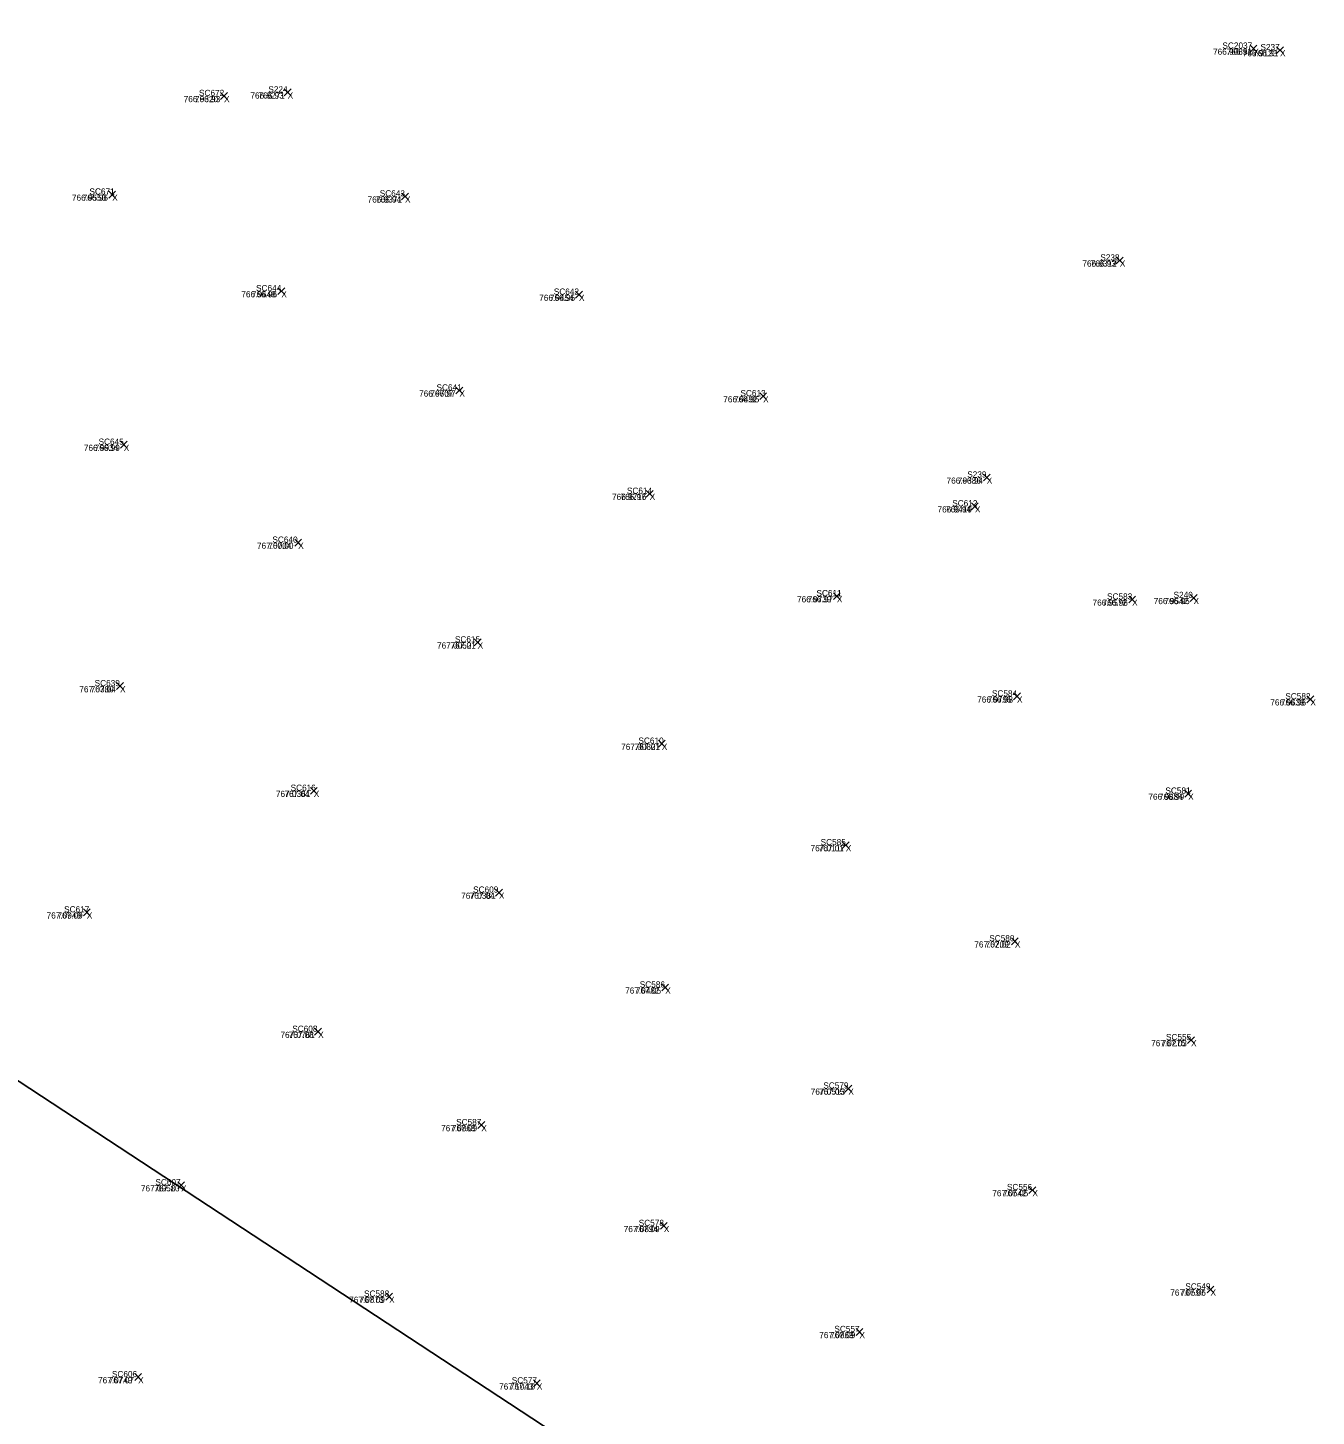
# Model space of a CAD drawing. Extents: x 1845019 to 1877956, y 680444 to 701081.
# Drawn here: x 1857624.26 to 1857636.8, y 694302.54 to 694316.04 of the extents above; entities that cross this region are included whole.
import ezdxf

# ---------------------------------------------------------------- set-up
doc = ezdxf.new("R2010")
doc.units = 0
for name, color, linetype in [('SV_X_CL_Survey_20', 7, 'Continuous'), ('SV_X_Random_Point', 7, 'Continuous'), ('SV_X_Text_Comment', 7, 'Continuous'), ('SV_X_Text_Elevation', 7, 'Continuous'), ('SV_X_Text_Name', 7, 'Continuous')]:
    doc.layers.add(name, color=color, linetype=linetype)

msp = doc.modelspace()

# ---------------------------------------------------------------- linework, layer by layer
at = {"layer": 'SV_X_CL_Survey_20'}
msp.add_line((1856038.267, 695346.314), (1858797.327, 693536.085), dxfattribs=at)
at = {"layer": 'SV_X_Random_Point'}
for p, q in [((1857636.153, 694315.809), (1857636.219, 694315.876)), ((1857636.153, 694315.876), (1857636.219, 694315.809)), ((1857636.153, 694315.809), (1857636.219, 694315.876)), ((1857636.153, 694315.876), (1857636.219, 694315.809)), ((1857636.411, 694315.794), (1857636.477, 694315.86)), ((1857636.411, 694315.86), (1857636.477, 694315.794)), ((1857636.411, 694315.794), (1857636.477, 694315.86)), ((1857636.411, 694315.86), (1857636.477, 694315.794)), ((1857626.14, 694315.347), (1857626.207, 694315.414)), ((1857626.14, 694315.414), (1857626.207, 694315.347)), ((1857626.14, 694315.347), (1857626.207, 694315.414)), ((1857626.14, 694315.414), (1857626.207, 694315.347)), ((1857626.758, 694315.383), (1857626.825, 694315.45)), ((1857626.758, 694315.45), (1857626.825, 694315.383)), ((1857626.758, 694315.383), (1857626.825, 694315.45)), ((1857626.758, 694315.45), (1857626.825, 694315.383)), ((1857625.053, 694314.388), (1857625.119, 694314.455)), ((1857625.053, 694314.455), (1857625.119, 694314.388)), ((1857625.053, 694314.388), (1857625.119, 694314.455)), ((1857625.053, 694314.455), (1857625.119, 694314.388)), ((1857627.9, 694314.371), (1857627.967, 694314.437)), ((1857627.9, 694314.437), (1857627.967, 694314.371)), ((1857627.9, 694314.371), (1857627.967, 694314.437)), ((1857627.9, 694314.437), (1857627.967, 694314.371)), ((1857634.852, 694313.747), (1857634.919, 694313.814)), ((1857634.852, 694313.814), (1857634.919, 694313.747)), ((1857634.852, 694313.747), (1857634.919, 694313.814)), ((1857634.852, 694313.814), (1857634.919, 694313.747)), ((1857626.697, 694313.449), (1857626.764, 694313.516)), ((1857626.697, 694313.516), (1857626.764, 694313.449)), ((1857626.697, 694313.449), (1857626.764, 694313.516)), ((1857626.697, 694313.516), (1857626.764, 694313.449)), ((1857629.593, 694313.414), (1857629.659, 694313.481)), ((1857629.593, 694313.481), (1857629.659, 694313.414)), ((1857629.593, 694313.414), (1857629.659, 694313.481)), ((1857629.593, 694313.481), (1857629.659, 694313.414)), ((1857628.429, 694312.482), (1857628.496, 694312.549)), ((1857628.429, 694312.549), (1857628.496, 694312.482)), ((1857628.429, 694312.482), (1857628.496, 694312.549)), ((1857628.429, 694312.549), (1857628.496, 694312.482)), ((1857631.384, 694312.427), (1857631.451, 694312.494)), ((1857631.384, 694312.494), (1857631.451, 694312.427)), ((1857631.384, 694312.427), (1857631.451, 694312.494)), ((1857631.384, 694312.494), (1857631.451, 694312.427)), ((1857625.165, 694311.955), (1857625.232, 694312.022)), ((1857625.165, 694312.022), (1857625.232, 694311.955)), ((1857625.165, 694311.955), (1857625.232, 694312.022)), ((1857625.165, 694312.022), (1857625.232, 694311.955)), ((1857633.559, 694311.636), (1857633.626, 694311.702)), ((1857633.559, 694311.702), (1857633.626, 694311.636)), ((1857633.559, 694311.636), (1857633.626, 694311.702)), ((1857633.559, 694311.702), (1857633.626, 694311.636)), ((1857630.28, 694311.477), (1857630.347, 694311.544)), ((1857630.28, 694311.544), (1857630.347, 694311.477)), ((1857630.28, 694311.477), (1857630.347, 694311.544)), ((1857630.28, 694311.544), (1857630.347, 694311.477)), ((1857633.444, 694311.356), (1857633.51, 694311.422)), ((1857633.444, 694311.422), (1857633.51, 694311.356)), ((1857633.444, 694311.356), (1857633.51, 694311.422)), ((1857633.444, 694311.422), (1857633.51, 694311.356)), ((1857626.861, 694311.002), (1857626.928, 694311.068)), ((1857626.861, 694311.068), (1857626.928, 694311.002)), ((1857626.861, 694311.002), (1857626.928, 694311.068)), ((1857626.861, 694311.068), (1857626.928, 694311.002)), ((1857632.101, 694310.481), (1857632.167, 694310.547)), ((1857632.101, 694310.547), (1857632.167, 694310.481)), ((1857632.101, 694310.481), (1857632.167, 694310.547)), ((1857632.101, 694310.547), (1857632.167, 694310.481)), ((1857634.973, 694310.449), (1857635.04, 694310.515)), ((1857634.973, 694310.515), (1857635.04, 694310.449)), ((1857634.973, 694310.449), (1857635.04, 694310.515)), ((1857634.973, 694310.515), (1857635.04, 694310.449)), ((1857635.57, 694310.464), (1857635.637, 694310.531)), ((1857635.57, 694310.531), (1857635.637, 694310.464)), ((1857635.57, 694310.464), (1857635.637, 694310.531)), ((1857635.57, 694310.531), (1857635.637, 694310.464)), ((1857628.607, 694310.031), (1857628.674, 694310.098)), ((1857628.607, 694310.098), (1857628.674, 694310.031)), ((1857628.607, 694310.031), (1857628.674, 694310.098)), ((1857628.607, 694310.098), (1857628.674, 694310.031)), ((1857625.128, 694309.606), (1857625.195, 694309.673)), ((1857625.128, 694309.673), (1857625.195, 694309.606)), ((1857625.128, 694309.606), (1857625.195, 694309.673)), ((1857625.128, 694309.673), (1857625.195, 694309.606)), ((1857633.852, 694309.506), (1857633.919, 694309.573)), ((1857633.852, 694309.573), (1857633.919, 694309.506)), ((1857633.852, 694309.506), (1857633.919, 694309.573)), ((1857633.852, 694309.573), (1857633.919, 694309.506)), ((1857636.706, 694309.478), (1857636.773, 694309.545)), ((1857636.706, 694309.545), (1857636.773, 694309.478)), ((1857636.706, 694309.478), (1857636.773, 694309.545)), ((1857636.706, 694309.545), (1857636.773, 694309.478)), ((1857630.398, 694309.045), (1857630.464, 694309.112)), ((1857630.398, 694309.112), (1857630.464, 694309.045)), ((1857630.398, 694309.045), (1857630.464, 694309.112)), ((1857630.398, 694309.112), (1857630.464, 694309.045)), ((1857627.013, 694308.587), (1857627.08, 694308.654)), ((1857627.013, 694308.654), (1857627.08, 694308.587)), ((1857627.013, 694308.587), (1857627.08, 694308.654)), ((1857627.013, 694308.654), (1857627.08, 694308.587)), ((1857635.517, 694308.559), (1857635.584, 694308.626)), ((1857635.517, 694308.626), (1857635.584, 694308.559)), ((1857635.517, 694308.559), (1857635.584, 694308.626)), ((1857635.517, 694308.626), (1857635.584, 694308.559)), ((1857632.187, 694308.059), (1857632.254, 694308.125)), ((1857632.187, 694308.125), (1857632.254, 694308.059)), ((1857632.187, 694308.059), (1857632.254, 694308.125)), ((1857632.187, 694308.125), (1857632.254, 694308.059)), ((1857628.814, 694307.597), (1857628.881, 694307.664)), ((1857628.814, 694307.664), (1857628.881, 694307.597)), ((1857628.814, 694307.597), (1857628.881, 694307.664)), ((1857628.814, 694307.664), (1857628.881, 694307.597)), ((1857624.806, 694307.404), (1857624.873, 694307.471)), ((1857624.806, 694307.471), (1857624.873, 694307.404)), ((1857624.806, 694307.404), (1857624.873, 694307.471)), ((1857624.806, 694307.471), (1857624.873, 694307.404)), ((1857633.832, 694307.122), (1857633.899, 694307.189)), ((1857633.832, 694307.189), (1857633.899, 694307.122)), ((1857633.832, 694307.122), (1857633.899, 694307.189)), ((1857633.832, 694307.189), (1857633.899, 694307.122)), ((1857630.432, 694306.674), (1857630.498, 694306.741)), ((1857630.432, 694306.741), (1857630.498, 694306.674)), ((1857630.432, 694306.674), (1857630.498, 694306.741)), ((1857630.432, 694306.741), (1857630.498, 694306.674)), ((1857627.055, 694306.243), (1857627.122, 694306.31)), ((1857627.055, 694306.31), (1857627.122, 694306.243)), ((1857627.055, 694306.243), (1857627.122, 694306.31)), ((1857627.055, 694306.31), (1857627.122, 694306.243)), ((1857635.546, 694306.162), (1857635.612, 694306.228)), ((1857635.546, 694306.228), (1857635.612, 694306.162)), ((1857635.546, 694306.162), (1857635.612, 694306.228)), ((1857635.546, 694306.228), (1857635.612, 694306.162)), ((1857632.212, 694305.69), (1857632.279, 694305.757)), ((1857632.212, 694305.757), (1857632.279, 694305.69)), ((1857632.212, 694305.69), (1857632.279, 694305.757)), ((1857632.212, 694305.757), (1857632.279, 694305.69)), ((1857628.642, 694305.335), (1857628.709, 694305.402)), ((1857628.642, 694305.402), (1857628.709, 694305.335)), ((1857628.642, 694305.335), (1857628.709, 694305.402)), ((1857628.642, 694305.402), (1857628.709, 694305.335)), ((1857625.723, 694304.75), (1857625.79, 694304.817)), ((1857625.723, 694304.817), (1857625.79, 694304.75)), ((1857625.723, 694304.75), (1857625.79, 694304.817)), ((1857625.723, 694304.817), (1857625.79, 694304.75)), ((1857634.002, 694304.703), (1857634.069, 694304.769)), ((1857634.002, 694304.769), (1857634.069, 694304.703)), ((1857634.002, 694304.703), (1857634.069, 694304.769)), ((1857634.002, 694304.769), (1857634.069, 694304.703)), ((1857630.418, 694304.354), (1857630.484, 694304.42)), ((1857630.418, 694304.42), (1857630.484, 694304.354)), ((1857630.418, 694304.354), (1857630.484, 694304.42)), ((1857630.418, 694304.42), (1857630.484, 694304.354)), ((1857627.746, 694303.666), (1857627.813, 694303.733)), ((1857627.746, 694303.733), (1857627.813, 694303.666)), ((1857627.746, 694303.666), (1857627.813, 694303.733)), ((1857627.746, 694303.733), (1857627.813, 694303.666)), ((1857635.735, 694303.736), (1857635.801, 694303.802)), ((1857635.735, 694303.802), (1857635.801, 694303.736)), ((1857635.735, 694303.736), (1857635.801, 694303.802)), ((1857635.735, 694303.802), (1857635.801, 694303.736)), ((1857632.321, 694303.321), (1857632.387, 694303.388)), ((1857632.321, 694303.388), (1857632.387, 694303.321)), ((1857632.321, 694303.321), (1857632.387, 694303.388)), ((1857632.321, 694303.388), (1857632.387, 694303.321)), ((1857625.305, 694302.883), (1857625.371, 694302.95)), ((1857625.305, 694302.95), (1857625.371, 694302.883)), ((1857625.305, 694302.883), (1857625.371, 694302.95)), ((1857625.305, 694302.95), (1857625.371, 694302.883)), ((1857629.182, 694302.822), (1857629.249, 694302.889)), ((1857629.182, 694302.889), (1857629.249, 694302.822)), ((1857629.182, 694302.822), (1857629.249, 694302.889)), ((1857629.182, 694302.889), (1857629.249, 694302.822))]:
    msp.add_line(p, q, dxfattribs=at)

# ---------------------------------------------------------------- texts
at = {"layer": 'SV_X_Text_Comment'}
for p in [(1857636.186, 694315.782), (1857636.444, 694315.767), (1857626.174, 694315.321), (1857626.792, 694315.356), (1857625.086, 694314.362), (1857627.934, 694314.344), (1857634.886, 694313.721), (1857626.731, 694313.422), (1857629.626, 694313.388), (1857628.463, 694312.456), (1857631.417, 694312.4), (1857625.198, 694311.928), (1857633.592, 694311.609), (1857630.313, 694311.451), (1857633.477, 694311.329), (1857626.895, 694310.975), (1857632.134, 694310.454), (1857635.006, 694310.422), (1857635.603, 694310.437), (1857628.64, 694310.005), (1857625.162, 694309.579), (1857633.886, 694309.479), (1857636.74, 694309.451), (1857630.431, 694309.019), (1857627.046, 694308.561), (1857635.551, 694308.533), (1857632.221, 694308.032), (1857628.847, 694307.57), (1857624.839, 694307.378), (1857633.866, 694307.096), (1857630.465, 694306.647), (1857627.089, 694306.216), (1857635.579, 694306.135), (1857632.246, 694305.664), (1857628.676, 694305.308), (1857625.756, 694304.723), (1857634.036, 694304.676), (1857630.451, 694304.327), (1857635.768, 694303.709), (1857627.779, 694303.639), (1857632.354, 694303.295), (1857625.338, 694302.856), (1857629.216, 694302.795)]:
    msp.add_text('X', height=0.06, dxfattribs=at).set_placement(p)
at = {"layer": 'SV_X_Text_Elevation'}
for s, p in [('766.9085', (1857635.793, 694315.782)), ('766.91', (1857635.926, 694315.782)), ('766.9123', (1857636.082, 694315.767)), ('766.91', (1857636.183, 694315.767)), ('766.9320', (1857625.781, 694315.321)), ('766.93', (1857625.891, 694315.321)), ('766.9271', (1857626.43, 694315.356)), ('766.93', (1857626.509, 694315.356)), ('766.9550', (1857624.694, 694314.362)), ('766.96', (1857624.799, 694314.362)), ('766.9371', (1857627.57, 694314.344)), ('766.94', (1857627.651, 694314.344)), ('766.9312', (1857634.522, 694313.721)), ('766.93', (1857634.603, 694313.721)), ('766.9648', (1857626.342, 694313.422)), ('766.96', (1857626.444, 694313.422)), ('766.9454', (1857629.239, 694313.388)), ('766.95', (1857629.343, 694313.388)), ('766.9707', (1857628.071, 694312.456)), ('766.97', (1857628.18, 694312.456)), ('766.9492', (1857631.029, 694312.4)), ('766.95', (1857631.134, 694312.4)), ('766.9934', (1857624.81, 694311.928)), ('766.99', (1857624.915, 694311.928)), ('766.9386', (1857633.201, 694311.609)), ('766.94', (1857633.31, 694311.609)), ('766.9716', (1857629.947, 694311.451)), ('766.97', (1857630.03, 694311.451)), ('766.9419', (1857633.113, 694311.329)), ('766.94', (1857633.195, 694311.329)), ('767.0004', (1857626.494, 694310.975)), ('767.00', (1857626.604, 694310.975)), ('766.9739', (1857631.747, 694310.454)), ('766.97', (1857631.851, 694310.454)), ('766.9572', (1857634.621, 694310.422)), ('766.96', (1857634.719, 694310.422)), ('766.9542', (1857635.216, 694310.437)), ('766.95', (1857635.32, 694310.437)), ('767.0052', (1857628.245, 694310.005)), ('767.01', (1857628.377, 694310.005)), ('767.0380', (1857624.766, 694309.579)), ('767.04', (1857624.876, 694309.579)), ('766.9795', (1857633.499, 694309.479)), ('766.98', (1857633.602, 694309.479)), ('766.9639', (1857636.35, 694309.451)), ('766.96', (1857636.453, 694309.451)), ('767.0082', (1857630.036, 694309.019)), ('767.01', (1857630.168, 694309.019)), ('767.0361', (1857626.678, 694308.561)), ('767.04', (1857626.761, 694308.561)), ('766.9884', (1857635.164, 694308.533)), ('766.99', (1857635.267, 694308.533)), ('767.0117', (1857631.878, 694308.032)), ('767.01', (1857631.957, 694308.032)), ('767.0381', (1857628.48, 694307.57)), ('767.04', (1857628.562, 694307.57)), ('767.0949', (1857624.448, 694307.378)), ('767.09', (1857624.553, 694307.378)), ('767.0209', (1857633.471, 694307.096)), ('767.02', (1857633.58, 694307.096)), ('767.0482', (1857630.075, 694306.647)), ('767.05', (1857630.179, 694306.647)), ('767.0761', (1857626.722, 694306.216)), ('767.08', (1857626.802, 694306.216)), ('767.0275', (1857635.191, 694306.135)), ('767.03', (1857635.293, 694306.135)), ('767.0513', (1857631.88, 694305.664)), ('767.05', (1857631.96, 694305.664)), ('767.0868', (1857628.285, 694305.308)), ('767.09', (1857628.389, 694305.308)), ('767.0958', (1857625.365, 694304.723)), ('767.10', (1857625.495, 694304.723)), ('767.0542', (1857633.646, 694304.676)), ('767.05', (1857633.75, 694304.676)), ('767.0894', (1857630.061, 694304.327)), ('767.09', (1857630.165, 694304.327)), ('767.0597', (1857635.377, 694303.709)), ('767.06', (1857635.478, 694303.709)), ('767.0873', (1857627.391, 694303.639)), ('767.09', (1857627.493, 694303.639)), ('767.0869', (1857631.963, 694303.295)), ('767.09', (1857632.068, 694303.295)), ('767.0749', (1857624.948, 694302.856)), ('767.07', (1857625.052, 694302.856)), ('767.1043', (1857628.849, 694302.795)), ('767.10', (1857628.954, 694302.795))]:
    msp.add_text(s, height=0.06, dxfattribs=at).set_placement(p)
at = {"layer": 'SV_X_Text_Name'}
for s, p in [('SC2037', (1857635.884, 694315.842)), ('SC2037', (1857635.884, 694315.842)), ('S237', (1857636.254, 694315.827)), ('S237', (1857636.254, 694315.827)), ('S224', (1857626.604, 694315.416)), ('S224', (1857626.604, 694315.416)), ('SC672', (1857625.93, 694315.381)), ('SC672', (1857625.93, 694315.381)), ('SC671', (1857624.864, 694314.422)), ('SC671', (1857624.865, 694314.422)), ('SC643', (1857627.688, 694314.404)), ('SC643', (1857627.688, 694314.404)), ('S238', (1857634.696, 694313.781)), ('S238', (1857634.696, 694313.781)), ('SC644', (1857626.485, 694313.482)), ('SC644', (1857626.485, 694313.482)), ('SC642', (1857629.381, 694313.448)), ('SC642', (1857629.381, 694313.448)), ('SC641', (1857628.24, 694312.516)), ('SC641', (1857628.24, 694312.516)), ('SC613', (1857631.196, 694312.46)), ('SC613', (1857631.196, 694312.46)), ('SC645', (1857624.953, 694311.988)), ('SC645', (1857624.953, 694311.988)), ('S239', (1857633.402, 694311.669)), ('S239', (1857633.402, 694311.669)), ('SC614', (1857630.092, 694311.511)), ('SC614', (1857630.092, 694311.511)), ('SC612', (1857633.256, 694311.389)), ('SC612', (1857633.256, 694311.389)), ('SC640', (1857626.644, 694311.035)), ('SC640', (1857626.644, 694311.035)), ('SC611', (1857631.936, 694310.514)), ('SC611', (1857631.935, 694310.514)), ('SC583', (1857634.762, 694310.482)), ('SC583', (1857634.762, 694310.482)), ('S240', (1857635.409, 694310.497)), ('S240', (1857635.409, 694310.497)), ('SC615', (1857628.419, 694310.065)), ('SC615', (1857628.419, 694310.065)), ('SC639', (1857624.915, 694309.639)), ('SC639', (1857624.915, 694309.639)), ('SC584', (1857633.642, 694309.539)), ('SC584', (1857633.642, 694309.539)), ('SC582', (1857636.496, 694309.511)), ('SC582', (1857636.496, 694309.511)), ('SC610', (1857630.204, 694309.079)), ('SC610', (1857630.204, 694309.079)), ('SC616', (1857626.821, 694308.621)), ('SC616', (1857626.821, 694308.621)), ('SC581', (1857635.329, 694308.593)), ('SC581', (1857635.33, 694308.593)), ('SC585', (1857631.976, 694308.092)), ('SC585', (1857631.976, 694308.092)), ('SC609', (1857628.596, 694307.63)), ('SC609', (1857628.596, 694307.63)), ('SC617', (1857624.618, 694307.438)), ('SC617', (1857624.618, 694307.438)), ('SC580', (1857633.616, 694307.156)), ('SC580', (1857633.616, 694307.156)), ('SC586', (1857630.217, 694306.707)), ('SC586', (1857630.217, 694306.707)), ('SC608', (1857626.837, 694306.276)), ('SC608', (1857626.837, 694306.276)), ('SC555', (1857635.335, 694306.195)), ('SC555', (1857635.335, 694306.195)), ('SC579', (1857632.002, 694305.724)), ('SC579', (1857632.002, 694305.724)), ('SC587', (1857628.431, 694305.368)), ('SC587', (1857628.431, 694305.368)), ('SC607', (1857625.506, 694304.783)), ('SC607', (1857625.506, 694304.783)), ('SC556', (1857633.788, 694304.736)), ('SC556', (1857633.788, 694304.736)), ('SC578', (1857630.207, 694304.387)), ('SC578', (1857630.207, 694304.387)), ('SC588', (1857627.535, 694303.699)), ('SC588', (1857627.535, 694303.699)), ('SC549', (1857635.523, 694303.769)), ('SC549', (1857635.523, 694303.769)), ('SC557', (1857632.11, 694303.355)), ('SC557', (1857632.11, 694303.355)), ('SC606', (1857625.083, 694302.916)), ('SC606', (1857625.083, 694302.916)), ('SC577', (1857628.972, 694302.855)), ('SC577', (1857628.972, 694302.855))]:
    msp.add_text(s, height=0.06, dxfattribs=at).set_placement(p)

doc.saveas('drawing.dxf')
